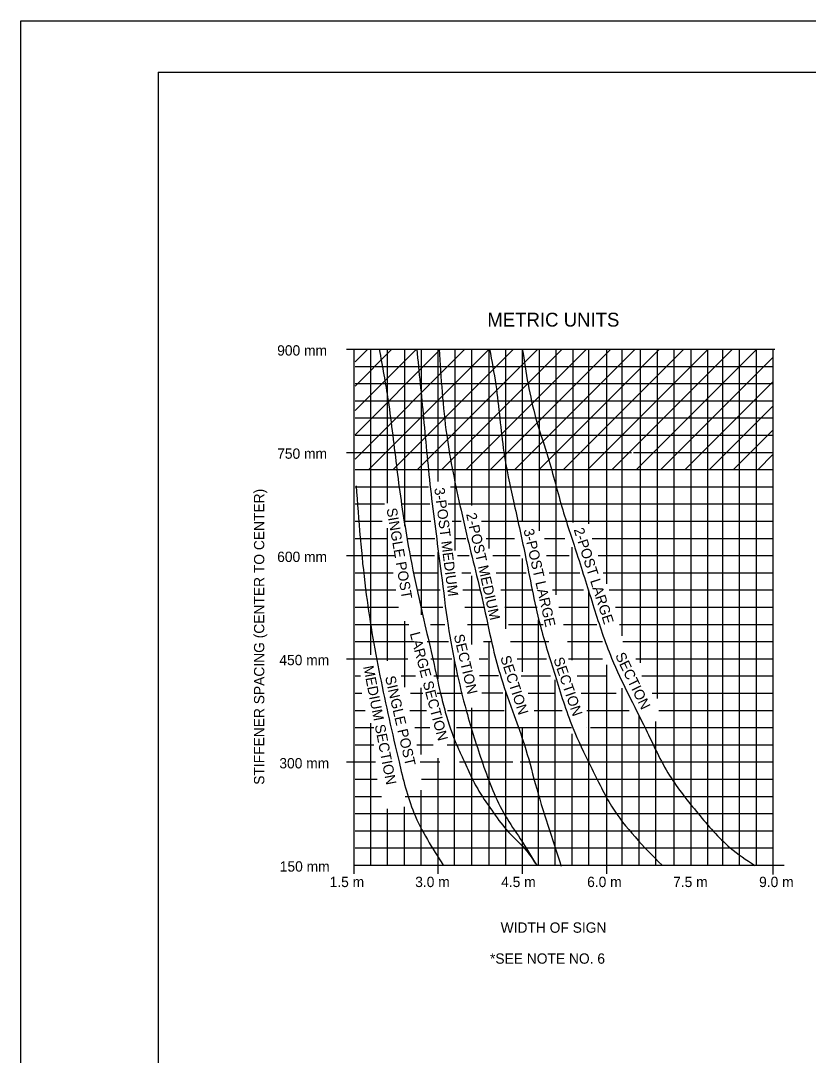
# Model space of a CAD drawing. Extents: x 650495 to 652241, y 298458 to 299646.
# Drawn here: x 650495.3 to 650724.3, y 299344.9 to 299645.6 of the extents above; entities that cross this region are included whole.
import ezdxf

# ---------------------------------------------------------------- set-up
doc = ezdxf.new("R2010")
doc.units = 0
for name, color, linetype in [('1', 7, 'Continuous'), ('2', 7, 'Continuous'), ('PLT-BNDY', 7, 'Continuous')]:
    doc.layers.add(name, color=color, linetype=linetype)

msp = doc.modelspace()

# ---------------------------------------------------------------- linework, layer by layer
at = {"layer": '1'}
for q in [(651321.31, 299630.63), (650535.31, 299066.63)]:
    msp.add_line((650535.31, 299630.63), q, dxfattribs=at)
at = {"layer": '2'}
for p, q in [((650590.03, 299550.15), (650714.65, 299550.15)), ((650592.53, 299546.47), (650596.21, 299550.15)), ((650592.53, 299539.4), (650603.28, 299550.15)), ((650592.53, 299532.33), (650610.36, 299550.15)), ((650592.53, 299525.25), (650617.43, 299550.15)), ((650592.53, 299518.18), (650624.5, 299550.15)), ((650595.28, 299550.15), (650595.28, 299550.15)), ((650596.57, 299515.15), (650631.57, 299550.15)), ((650603.64, 299515.15), (650638.64, 299550.15)), ((650607.53, 299550.15), (650607.53, 299550.15)), ((650610.71, 299515.15), (650645.71, 299550.15)), ((650617.78, 299515.15), (650652.78, 299550.15)), ((650624.85, 299515.15), (650659.85, 299550.15)), ((650625.9, 299550.15), (650625.9, 299550.15)), ((650631.28, 299550.15), (650631.28, 299550.15)), ((650631.92, 299515.15), (650666.92, 299550.15)), ((650639, 299515.15), (650674, 299550.15)), ((650646.07, 299515.15), (650681.07, 299550.15)), ((650653.14, 299515.15), (650688.14, 299550.15)), ((650660.21, 299515.15), (650695.21, 299550.15)), ((650661.15, 299550.15), (650661.15, 299550.15)), ((650667.28, 299515.15), (650702.28, 299550.15)), ((650674.35, 299515.15), (650709.35, 299550.15)), ((650681.42, 299515.15), (650714.03, 299547.76)), ((650592.53, 299545.15), (650714.03, 299545.15)), ((650607.53, 299545.15), (650607.53, 299545.15)), ((650632.53, 299542.53), (650632.53, 299542.53)), ((650592.53, 299540.15), (650714.03, 299540.15)), ((650688.49, 299515.15), (650714.03, 299540.69)), ((650592.53, 299535.15), (650714.03, 299535.15)), ((650633.65, 299535.15), (650633.65, 299535.15)), ((650695.56, 299515.15), (650714.03, 299533.62)), ((650592.53, 299530.15), (650714.03, 299530.15)), ((650627.53, 299530.15), (650627.53, 299530.15)), ((650665.15, 299530.15), (650665.15, 299530.15)), ((650702.63, 299515.15), (650714.03, 299526.55)), ((650592.53, 299525.15), (650714.03, 299525.15)), ((650590.03, 299520.15), (650672.9, 299520.15)), ((650597.53, 299520.15), (650597.53, 299520.15)), ((650636.78, 299520.15), (650636.78, 299520.15)), ((650673.53, 299520.15), (650714.03, 299520.15)), ((650709.71, 299515.15), (650714.03, 299519.48)), ((650592.53, 299515.15), (650714.03, 299515.15)), ((650609.9, 299515.15), (650609.9, 299515.15)), ((650592.53, 299510.15), (650613.94, 299510.15)), ((650620.28, 299510.15), (650714.03, 299510.15)), ((650592.53, 299505.15), (650601.15, 299505.15)), ((650605.9, 299505.15), (650614.33, 299505.15)), ((650619.59, 299505.15), (650714.03, 299505.15)), ((650592.53, 299500.15), (650600.46, 299500.15)), ((650606.9, 299500.15), (650614.53, 299500.15)), ((650612.53, 299500.15), (650612.53, 299500.15)), ((650620.77, 299500.15), (650623.35, 299500.15)), ((650629.3, 299500.15), (650714.03, 299500.15)), ((650592.53, 299495.15), (650601.85, 299495.15)), ((650607.78, 299495.15), (650615.72, 299495.15)), ((650621.67, 299495.15), (650624.74, 299495.15)), ((650630.68, 299495.15), (650638.9, 299495.15)), ((650647.62, 299495.15), (650653.57, 299495.15)), ((650661.5, 299495.15), (650714.03, 299495.15)), ((650590.03, 299490.15), (650604.15, 299490.15)), ((650608.78, 299490.15), (650615.62, 299490.15)), ((650622.36, 299490.15), (650625.73, 299490.15)), ((650632.57, 299490.15), (650640.53, 299490.15)), ((650648.22, 299490.15), (650654.76, 299490.15)), ((650663.28, 299490.15), (650714.03, 299490.15)), ((650592.53, 299485.15), (650603.63, 299485.15)), ((650609.65, 299485.15), (650616.65, 299485.15)), ((650623.55, 299485.15), (650626.22, 299485.15)), ((650633.56, 299485.15), (650642.28, 299485.15)), ((650647.53, 299485.15), (650647.53, 299485.15)), ((650649.01, 299485.15), (650657.93, 299485.15)), ((650664.67, 299485.15), (650714.03, 299485.15)), ((650592.53, 299480.15), (650604.43, 299480.15)), ((650610.65, 299480.15), (650617.31, 299480.15)), ((650623.85, 299480.15), (650628.8, 299480.15)), ((650634.94, 299480.15), (650643.9, 299480.15)), ((650650, 299480.15), (650658.92, 299480.15)), ((650666.45, 299480.15), (650714.03, 299480.15)), ((650592.53, 299475.15), (650605.22, 299475.15)), ((650611.65, 299475.15), (650618.1, 299475.15)), ((650624.44, 299475.15), (650629.99, 299475.15)), ((650636.13, 299475.15), (650645.53, 299475.15)), ((650651.79, 299475.15), (650660.31, 299475.15)), ((650668.23, 299475.15), (650714.03, 299475.15)), ((650592.53, 299470.15), (650608.15, 299470.15)), ((650614.43, 299470.15), (650618.6, 299470.15)), ((650625.23, 299470.15), (650631.38, 299470.15)), ((650637.12, 299470.15), (650647.28, 299470.15)), ((650653.17, 299470.15), (650662.88, 299470.15)), ((650669.42, 299470.15), (650714.03, 299470.15)), ((650592.53, 299465.15), (650609.15, 299465.15)), ((650607.53, 299465.15), (650607.53, 299465.15)), ((650613.53, 299465.15), (650619.69, 299465.15)), ((650629.9, 299465.15), (650632.37, 299465.15)), ((650637.72, 299465.15), (650648.9, 299465.15)), ((650654.36, 299465.15), (650664.47, 299465.15)), ((650670.41, 299465.15), (650714.03, 299465.15)), ((650590.03, 299460.15), (650607.9, 299460.15)), ((650592.53, 299460.15), (650592.53, 299460.15)), ((650614.53, 299460.15), (650620.68, 299460.15)), ((650628.6, 299460.15), (650631.18, 299460.15)), ((650639.7, 299460.15), (650648.22, 299460.15)), ((650648.78, 299460.15), (650648.78, 299460.15)), ((650654.65, 299460.15), (650664.47, 299460.15)), ((650674.18, 299460.15), (650714.03, 299460.15)), ((650592.53, 299455.15), (650594.12, 299455.15)), ((650605.91, 299455.15), (650610.07, 299455.15)), ((650615.4, 299455.15), (650622.36, 299455.15)), ((650634.25, 299455.15), (650628.7, 299455.15)), ((650640.89, 299455.15), (650649.41, 299455.15)), ((650657.14, 299455.15), (650665.85, 299455.15)), ((650675.96, 299455.15), (650714.03, 299455.15)), ((650592.53, 299450.15), (650594.52, 299450.15)), ((650608.69, 299450.15), (650612.28, 299450.15)), ((650616.4, 299450.15), (650623.75, 299450.15)), ((650635.54, 299450.15), (650629.39, 299450.15)), ((650642.87, 299450.15), (650650.6, 299450.15)), ((650658.32, 299450.15), (650668.43, 299450.15)), ((650678.93, 299450.15), (650714.03, 299450.15)), ((650592.53, 299445.15), (650595.51, 299445.15)), ((650608.49, 299445.15), (650613.28, 299445.15)), ((650619.39, 299445.15), (650635.93, 299445.15)), ((650644.65, 299445.15), (650652.78, 299445.15)), ((650659.91, 299445.15), (650672.2, 299445.15)), ((650680.91, 299445.15), (650714.03, 299445.15)), ((650708.9, 299445.15), (650708.9, 299445.15)), ((650592.53, 299440.15), (650598.03, 299440.15)), ((650609.88, 299440.15), (650614.28, 299440.15)), ((650612.53, 299440.15), (650612.53, 299440.15)), ((650622.06, 299440.15), (650655.45, 299440.15)), ((650659.9, 299440.15), (650659.9, 299440.15)), ((650661, 299440.15), (650714.03, 299440.15)), ((650592.53, 299435.15), (650597.99, 299435.15)), ((650610.47, 299435.15), (650615.28, 299435.15)), ((650619.28, 299435.15), (650714.03, 299435.15)), ((650590.03, 299430.15), (650598.48, 299430.15)), ((650597.53, 299430.15), (650597.53, 299430.15)), ((650611.46, 299430.15), (650617.21, 299430.15)), ((650622.95, 299430.15), (650638.4, 299430.15)), ((650640.53, 299430.15), (650714.03, 299430.15)), ((650592.53, 299425.15), (650598.98, 299425.15)), ((650611.86, 299425.15), (650714.03, 299425.15)), ((650592.53, 299420.15), (650600.27, 299420.15)), ((650607.15, 299420.15), (650714.03, 299420.15)), ((650642.53, 299420.15), (650642.53, 299420.15)), ((650686.78, 299420.15), (650686.78, 299420.15)), ((650592.53, 299415.15), (650714.03, 299415.15)), ((650692.53, 299415.15), (650692.53, 299415.15)), ((650592.53, 299410.15), (650714.03, 299410.15)), ((650627.53, 299410.15), (650627.53, 299410.15)), ((650650.15, 299410.15), (650650.15, 299410.15)), ((650687.53, 299410.15), (650687.53, 299410.15)), ((650699.9, 299410.15), (650699.9, 299410.15)), ((650592.53, 299405.15), (650714.03, 299405.15)), ((650607.53, 299405.15), (650607.53, 299405.15)), ((650592.15, 299400.15), (650717.28, 299400.15)), ((650712.53, 299400.15), (650712.53, 299400.15))]:
    msp.add_line(p, q, dxfattribs=at)
for points in [[(650592.15, 299550.15), (650592.15, 299397.65)], [(650597.03, 299550.15), (650597.03, 299461.28)], [(650601.9, 299550.15), (650601.9, 299505.41)], [(650606.9, 299550.15), (650606.9, 299498.65)], [(650611.78, 299550.15), (650611.78, 299472.9)], [(650616.65, 299550.15), (650616.65, 299511.65)], [(650621.53, 299550.15), (650621.53, 299491.63)], [(650626.4, 299550.15), (650626.4, 299504.72)], [(650631.4, 299550.15), (650631.4, 299492.23)], [(650636.28, 299550.15), (650636.28, 299468.84)], [(650641.15, 299550.15), (650641.15, 299500.03)], [(650646.03, 299550.15), (650646.03, 299497.38)], [(650650.9, 299550.15), (650650.9, 299478.75)], [(650655.9, 299550.15), (650655.9, 299499.76)], [(650660.4, 299550.15), (650660.4, 299499.36)], [(650665.65, 299550.15), (650665.65, 299481.92)], [(650670.15, 299550.15), (650670.15, 299466.86)], [(650675.4, 299550.15), (650675.4, 299458.93)], [(650680.4, 299550.15), (650680.4, 299448.63)], [(650685.28, 299550.15), (650685.28, 299400.15)], [(650690.15, 299550.15), (650690.15, 299400.15)], [(650695.03, 299550.15), (650695.03, 299400.15)], [(650699.4, 299550.15), (650699.4, 299400.15)], [(650704.28, 299550.15), (650704.28, 299400.15)], [(650709.15, 299550.15), (650709.15, 299400.15)], [(650714.03, 299550.15), (650714.03, 299397.44)], [(650601.9, 299498.08), (650601.9, 299459.53)], [(650616.65, 299491.14), (650616.65, 299454.27)], [(650655.53, 299492.63), (650655.53, 299459.72)], [(650641.15, 299489.28), (650641.15, 299456.35)], [(650626.4, 299484.3), (650626.4, 299464.28)], [(650660.4, 299480.14), (650660.4, 299400.15)], [(650606.9, 299471.12), (650606.9, 299451.9)], [(650645.78, 299471.42), (650645.78, 299400.15)], [(650631.4, 299465.27), (650631.4, 299400.15)], [(650621.4, 299459.72), (650621.4, 299400.15)], [(650665.65, 299458.34), (650665.65, 299397.65)], [(650650.65, 299453.98), (650650.65, 299400.15)], [(650611.65, 299451.65), (650611.65, 299432.27)], [(650670.15, 299451.6), (650670.15, 299400.15)], [(650636.28, 299450.61), (650636.28, 299400.15)], [(650626.4, 299445.85), (650626.4, 299400.15)], [(650675.03, 299443.67), (650675.03, 299400.15)], [(650679.9, 299441.89), (650679.9, 299400.15)], [(650597.03, 299441.39), (650597.03, 299400.15)], [(650641.15, 299440.3), (650641.15, 299397.65)], [(650655.53, 299438.32), (650655.53, 299400.15)], [(650616.65, 299431.28), (650616.65, 299397.65)], [(650611.65, 299421.97), (650611.65, 299400.15)], [(650601.9, 299416.52), (650601.9, 299400.15)], [(650606.78, 299417.11), (650606.78, 299400.15)]]:
    msp.add_lwpolyline(points, dxfattribs=at)
for points in [[(650599.57, 299550.15), (650602.15, 299535.24), (650604.72, 299515.02), (650607.7, 299494.81), (650610.47, 299480.54), (650612.85, 299470.03), (650615.23, 299459.72), (650617.41, 299450.01), (650618.79, 299444.66), (650622.16, 299434.95), (650624.14, 299430.59), (650626.52, 299425.44), (650629.3, 299420.48), (650632.27, 299416.12), (650636.63, 299410.37), (650641.98, 299404.82), (650645.35, 299400.15)], [(650610.47, 299550.15), (650612.45, 299530.09), (650614.63, 299508.09), (650617.6, 299484.9), (650619.59, 299469.83), (650624.94, 299444.86), (650629.69, 299429.6), (650636.23, 299414.53), (650640.59, 299407.8), (650645.35, 299400.15)], [(650617.01, 299550.15), (650619.19, 299525.15), (650623.35, 299503.33), (650624.94, 299496.39), (650630.09, 299474.99), (650632.66, 299463.19), (650635.04, 299454.57), (650638.81, 299443.67), (650641.78, 299435.15), (650644.95, 299423.85), (650652.48, 299399.87)], [(650631.67, 299550.15), (650633.46, 299539.8), (650635.83, 299520.18), (650638.61, 299505.91), (650641.98, 299490.45), (650646.34, 299470.03), (650650.7, 299455.36), (650655.85, 299440.1), (650661, 299429), (650664.17, 299422.66), (650667.14, 299417.31), (650681.81, 299400.15)], [(650641.18, 299550.15), (650645.15, 299529.89), (650648.32, 299519.78), (650652.68, 299504.32), (650657.04, 299490.64), (650661.99, 299474.99), (650667.14, 299460.32), (650677.05, 299439.71), (650683.99, 299426.23), (650692.31, 299415.13), (650701.62, 299405.22), (650708.75, 299400.07)], [(650592.84, 299510.46), (650595.61, 299480.34), (650599.77, 299455.17), (650605.32, 299430.19), (650609.68, 299415.33), (650618.2, 299400.15)]]:
    msp.add_spline(points, degree=3, dxfattribs=at)
at = {"layer": 'PLT-BNDY'}
msp.add_lwpolyline([(650495.31, 299645.63), (651336.31, 299645.63), (651336.31, 299051.63), (650495.31, 299051.63)], close=True, dxfattribs=at)

# ---------------------------------------------------------------- texts
at = {"layer": '2'}
for s, height, p in [('METRIC UNITS', 4.0375, (650631.01, 299556.7)), ('900 mm', 3, (650569.9, 299548.28)), ('750 mm', 3, (650569.9, 299518.28)), ('600 mm', 3, (650569.9, 299488.28)), ('450 mm', 3, (650570.53, 299458.28)), ('300 mm', 3, (650570.53, 299428.28)), ('150 mm', 3, (650570.65, 299398.28)), ('1.5 m', 3, (650585.15, 299393.78)), ('3.0 m', 3, (650610.03, 299393.78)), ('4.5 m', 3, (650635.03, 299393.78)), ('6.0 m', 3, (650660.03, 299393.78)), ('7.5 m', 3, (650685.03, 299393.78)), ('9.0 m', 3, (650710.03, 299393.78)), ('WIDTH OF SIGN', 3, (650634.88, 299380.5)), ('*SEE NOTE NO. 6', 3, (650631.78, 299371.5))]:
    msp.add_text(s, height=height, dxfattribs=at).set_placement(p)
for s, height, rotation, p in [('STIFFENER SPACING (CENTER TO CENTER)', 3, 90, (650566.15, 299423.52)), ('3-POST MEDIUM', 2.9992, 277.2906, (650615.57, 299509.72)), ('SINGLE POST', 3, 279.7906, (650601.68, 299503.73)), ('2-POST MEDIUM', 3, 282.7906, (650624.81, 299502.21)), ('3-POST LARGE', 3, 282.7906, (650641.5, 299497.61)), ('2-POST LARGE', 3, 287.7906, (650656.08, 299497.71)), ('LARGE SECTION', 3, 284.7906, (650608.43, 299467.5)), ('SECTION', 2.999, 283.2906, (650621.22, 299466.94)), ('SECTION', 3, 287.7906, (650634.73, 299460.54)), ('SECTION', 3, 288.7906, (650650.18, 299460.04)), ('SECTION', 3, 295.7906, (650668.11, 299461.12)), ('MEDIUM SECTION', 3, 281.0612, (650594.91, 299457.85)), ('SINGLE POST', 3, 283.0612, (650601.24, 299454.83))]:
    msp.add_text(s, height=height, rotation=rotation, dxfattribs=at).set_placement(p)

doc.saveas('drawing.dxf')
